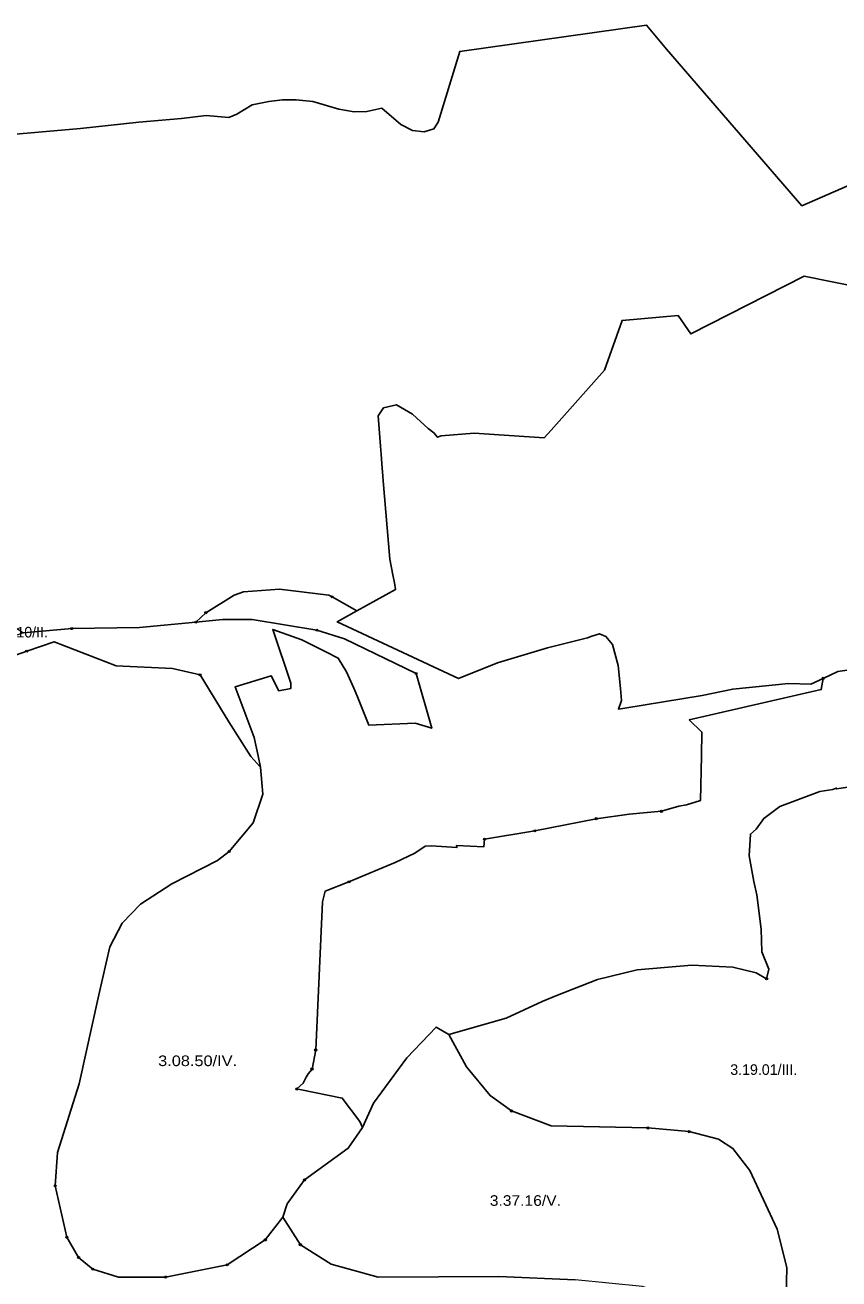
# Model space of a CAD drawing. Extents: x -650455 to -642254, y -1075222 to -1066610.
# Drawn here: x -644838 to -644071, y -1069625 to -1068444 of the extents above; entities that cross this region are included whole.
import ezdxf
from ezdxf.enums import TextEntityAlignment as Align

# ---------------------------------------------------------------- set-up
doc = ezdxf.new("R2010")
doc.units = 0
doc.header["$LTSCALE"] = 4
doc.header["$PDMODE"] = 32
doc.header["$PDSIZE"] = 2
for name, color, linetype, lineweight in [('1', 7, 'Continuous', 25), ('11', 7, 'Continuous', 13), ('13', 7, 'Continuous', 13), ('14', 7, 'Continuous', 13), ('15', 7, 'Continuous', 13), ('16', 7, 'Continuous', 13)]:
    doc.layers.add(name, color=color, linetype=linetype, lineweight=lineweight)
doc.layers.add('2', color=7, linetype='Continuous')

msp = doc.modelspace()

# ---------------------------------------------------------------- linework, layer by layer
at = {"layer": '1'}
for points in [[(-644865.029, -1068548.219), (-644785.549, -1068541.387), (-644730.78, -1068535.476), (-644690.424, -1068532.018), (-644667.364, -1068529.135), (-644646.033, -1068530.865), (-644638.25, -1068527.839), (-644623.837, -1068518.903), (-644608.271, -1068515.731), (-644595.299, -1068514.291), (-644582.328, -1068514.291), (-644566.762, -1068515.875), (-644542.26, -1068523.081), (-644527.847, -1068525.533), (-644515.877, -1068525.233), (-644501.596, -1068522.127), (-644483.899, -1068537.657), (-644472.722, -1068543.249), (-644461.856, -1068544.49), (-644452.542, -1068541.695), (-644448.506, -1068535.484), (-644428.326, -1068468.706), (-644252.29, -1068443.858), (-644233.352, -1068466.531)], [(-644233.352, -1068466.531), (-644105.749, -1068614.065), (-644012.919, -1068573.686)], [(-644024.406, -1068696.372), (-644103.575, -1068680.531), (-644210.376, -1068734.886), (-644222.484, -1068717.492), (-644275.263, -1068722.151), (-644291.718, -1068769.051), (-644342.212, -1068825.639), (-644348.534, -1068832.723), (-644414.741, -1068828.435), (-644445.788, -1068830.92), (-644449.35, -1068832.01), (-644452.802, -1068828.111), (-644458.176, -1068823.819), (-644472.804, -1068810.471), (-644488.017, -1068801.775), (-644500.125, -1068804.57), (-644505.092, -1068812.026), (-644502.911, -1068840.68), (-644502.338, -1068848.206), (-644501.654, -1068857.202), (-644500.772, -1068868.778), (-644500.435, -1068873.213), (-644494.115, -1068947.011), (-644491.207, -1068961.854), (-644489.705, -1068969.518), (-644488.773, -1068975.73), (-644525.181, -1068995.897), (-644548.5, -1068982.501), (-644551.5, -1068981.001), (-644598, -1068975.5), (-644632, -1068978.001), (-644641, -1068981.001), (-644667.5, -1068997.501), (-644677, -1069006.501), (-644730, -1069011.5), (-644794, -1069012.5)], [(-644640, -1069067.501), (-644606, -1069057), (-644598.81, -1069071.02), (-644587.5, -1069069), (-644587.5, -1069064), (-644604.5, -1069013.501), (-644577, -1069023.001), (-644555, -1069034.001), (-644543, -1069040.5), (-644535.13, -1069053.181), (-644529.464, -1069065.769), (-644528, -1069068.5), (-644526.232, -1069072.948), (-644525.83, -1069073.84), (-644525.345, -1069075.177), (-644514.093, -1069103.478), (-644470.37, -1069101.551), (-644454.63, -1069106.281), (-644469.28, -1069054.8), (-644537, -1069022.001), (-644563, -1069014.001), (-644624, -1069004), (-644652, -1069004), (-644677, -1069006.501), (-644667.5, -1068997.501), (-644641, -1068981.001), (-644632, -1068978.001), (-644598, -1068975.5), (-644551.5, -1068981.001), (-644548.5, -1068982.501), (-644525.181, -1068995.897)], [(-644839.5, -1069016.5), (-644794, -1069012.5), (-644730, -1069011.5), (-644677, -1069006.501), (-644652, -1069004), (-644624, -1069004), (-644563, -1069014.001), (-644537, -1069022.001), (-644469.28, -1069054.8), (-644454.63, -1069106.281), (-644470.37, -1069101.551), (-644514.093, -1069103.478), (-644525.345, -1069075.177), (-644525.83, -1069073.84), (-644526.232, -1069072.948), (-644528, -1069068.5), (-644529.464, -1069065.769), (-644535.13, -1069053.181), (-644543, -1069040.5)], [(-644525.181, -1068995.897), (-644543.726, -1069006.168), (-644429.474, -1069059.592), (-644392.528, -1069044.683), (-644345.647, -1069030.706), (-644307.77, -1069021.078), (-644303.667, -1069019.725), (-644296.6, -1069017.395), (-644290.701, -1069019.88), (-644284.181, -1069027.644), (-644278.903, -1069047.211), (-644276.818, -1069069.004), (-644275.887, -1069080.185), (-644278.515, -1069088.547), (-644272.734, -1069087.604), (-644199.819, -1069075.69), (-644170.945, -1069069.479), (-644118.477, -1069064.198), (-644097.468, -1069064.949), (-644085.664, -1069059.379), (-644087.5, -1069070.001), (-644212, -1069098.501), (-644200, -1069110), (-644200.5, -1069132.5), (-644201.5, -1069174.5), (-644214.53, -1069178.601), (-644221.69, -1069179.9), (-644238.23, -1069184.641), (-644268.7, -1069187.421), (-644299.717, -1069191.596), (-644357.5, -1069203), (-644405, -1069211), (-644405.5, -1069218), (-644431.362, -1069216.923), (-644430.91, -1069218.821), (-644454.87, -1069217.05), (-644460.97, -1069217.61), (-644470.64, -1069224.001), (-644489.27, -1069233.04), (-644532.71, -1069251.121)], [(-644794, -1069012.5), (-644839.5, -1069016.5)], [(-644543, -1069040.5), (-644555, -1069034.001), (-644577, -1069023.001), (-644604.5, -1069013.501), (-644587.5, -1069064), (-644587.5, -1069069), (-644598.81, -1069071.02), (-644606, -1069057), (-644640, -1069067.501), (-644622, -1069115.001), (-644618.28, -1069132.421), (-644616, -1069143.001)], [(-644616, -1069143.001), (-644625, -1069133), (-644646, -1069100.5), (-644673, -1069056), (-644699, -1069050.001), (-644752, -1069047.5), (-644810.5, -1069025), (-644836.38, -1069033.691), (-644871, -1069046.001)], [(-644871, -1069046.001), (-644836.38, -1069033.691), (-644810.5, -1069025), (-644752, -1069047.5), (-644699, -1069050.001)], [(-644699, -1069050.001), (-644673, -1069056), (-644646, -1069100.5), (-644625, -1069133), (-644616, -1069143.001)], [(-644357.5, -1069203), (-644299.717, -1069191.596), (-644268.7, -1069187.421), (-644238.23, -1069184.641), (-644221.69, -1069179.9), (-644214.53, -1069178.601), (-644201.5, -1069174.5), (-644200.5, -1069132.5), (-644200, -1069110), (-644212, -1069098.501), (-644087.5, -1069070.001), (-644085.664, -1069059.379), (-644071.881, -1069052.874), (-644052.196, -1069050.206), (-644019.287, -1069058.281), (-643971.567, -1069076.484)], [(-644532.71, -1069251.121), (-644555, -1069260), (-644557.5, -1069270.001), (-644564, -1069409.5), (-644567.5, -1069427.501), (-644571, -1069432.001), (-644572.97, -1069435.121), (-644575.93, -1069440.66), (-644581.87, -1069446.281), (-644578.92, -1069446.801), (-644539, -1069454.881), (-644522.5, -1069477), (-644520, -1069482.5), (-644533.5, -1069502), (-644574.5, -1069532.001), (-644591, -1069554.5), (-644595, -1069567), (-644611.5, -1069588.501), (-644647.5, -1069612), (-644705.5, -1069623.5), (-644750, -1069623.5), (-644774, -1069616), (-644787.5, -1069605.001), (-644798.5, -1069586), (-644809.5, -1069537.5), (-644807.5, -1069506), (-644787, -1069441.5), (-644768.5, -1069357.501), (-644758, -1069312.5), (-644746.5, -1069290.001), (-644729, -1069272), (-644699.5, -1069253.001), (-644656.5, -1069231), (-644645.5, -1069222.5), (-644623, -1069195.501), (-644614, -1069168.501), (-644616, -1069143.001), (-644618.28, -1069132.421), (-644622, -1069115.001), (-644640, -1069067.501)], [(-644616, -1069143.001), (-644614, -1069168.501), (-644623, -1069195.501), (-644645.5, -1069222.5), (-644656.5, -1069231), (-644699.5, -1069253.001), (-644729, -1069272), (-644746.5, -1069290.001), (-644758, -1069312.5), (-644768.5, -1069357.501), (-644787, -1069441.5), (-644807.5, -1069506), (-644809.5, -1069537.5), (-644798.5, -1069586), (-644787.5, -1069605.001), (-644774, -1069616), (-644750, -1069623.5), (-644705.5, -1069623.5), (-644647.5, -1069612), (-644611.5, -1069588.501), (-644595, -1069567), (-644578.5, -1069593.001), (-644549.5, -1069611.5), (-644505, -1069623.5), (-644391.5, -1069623), (-644319.5, -1069626.001)], [(-644209.5, -1069329.501), (-644171, -1069331.5), (-644149, -1069337.001), (-644139, -1069342.501), (-644137, -1069333.501), (-644143.54, -1069317.051), (-644144.05, -1069295.67), (-644148.22, -1069263.22), (-644151.11, -1069250.7), (-644155.37, -1069226.72), (-644154.36, -1069206.06), (-644148.931, -1069201.554), (-644141.5, -1069191.501), (-644126.5, -1069180.001), (-644089, -1069166), (-644076.643, -1069164.135), (-644073.35, -1069162.84), (-644073.229, -1069163.62), (-644062.5, -1069162)], [(-644062.5, -1069162), (-644073.229, -1069163.62), (-644073.35, -1069162.84), (-644076.643, -1069164.135), (-644089, -1069166), (-644126.5, -1069180.001), (-644141.5, -1069191.501), (-644148.931, -1069201.554), (-644154.36, -1069206.06), (-644155.37, -1069226.72), (-644151.11, -1069250.7)], [(-644151.11, -1069250.7), (-644148.22, -1069263.22), (-644144.05, -1069295.67), (-644143.54, -1069317.051), (-644137, -1069333.501), (-644139, -1069342.501), (-644149, -1069337.001), (-644171, -1069331.5), (-644209.5, -1069329.501), (-644261, -1069334.001), (-644298.5, -1069343), (-644337.6, -1069358.4), (-644350.5, -1069364), (-644384.5, -1069379.5), (-644438.5, -1069395.001), (-644450.5, -1069388), (-644478, -1069417), (-644509.5, -1069459.501), (-644520, -1069482.5), (-644522.5, -1069477), (-644539, -1069454.881), (-644578.92, -1069446.801), (-644581.87, -1069446.281), (-644575.93, -1069440.66), (-644572.97, -1069435.121), (-644571, -1069432.001), (-644567.5, -1069427.501), (-644564, -1069409.5), (-644557.5, -1069270.001), (-644555, -1069260), (-644532.71, -1069251.121), (-644489.27, -1069233.04), (-644470.64, -1069224.001), (-644460.97, -1069217.61), (-644454.87, -1069217.05), (-644430.91, -1069218.821), (-644431.362, -1069216.923), (-644405.5, -1069218), (-644405, -1069211), (-644357.5, -1069203)], [(-644121, -1069656), (-644120, -1069614.5), (-644129, -1069578.5), (-644155, -1069523), (-644171, -1069502.5), (-644184.5, -1069493.5), (-644212, -1069486.5), (-644251, -1069483.001), (-644342, -1069481), (-644379.5, -1069467.001), (-644399.5, -1069452.5), (-644422, -1069425.5), (-644438.5, -1069395.001), (-644384.5, -1069379.5), (-644350.5, -1069364), (-644337.6, -1069358.4), (-644298.5, -1069343), (-644261, -1069334.001), (-644209.5, -1069329.501)], [(-644319.5, -1069626.001), (-644391.5, -1069623), (-644505, -1069623.5), (-644549.5, -1069611.5), (-644578.5, -1069593.001), (-644595, -1069567), (-644591, -1069554.5), (-644574.5, -1069532.001), (-644533.5, -1069502), (-644520, -1069482.5), (-644509.5, -1069459.501), (-644478, -1069417), (-644450.5, -1069388), (-644438.5, -1069395.001), (-644422, -1069425.5), (-644399.5, -1069452.5), (-644379.5, -1069467.001), (-644342, -1069481), (-644251, -1069483.001), (-644212, -1069486.5), (-644184.5, -1069493.5), (-644171, -1069502.5), (-644155, -1069523), (-644129, -1069578.5), (-644120, -1069614.5), (-644121, -1069656)]]:
    msp.add_lwpolyline(points, dxfattribs=at)
at = {"layer": '11'}
for points in [[(-644012.919, -1068573.686), (-644105.749, -1068614.065), (-644233.352, -1068466.531), (-644252.29, -1068443.858), (-644428.326, -1068468.706), (-644448.506, -1068535.484)], [(-644448.506, -1068535.484), (-644452.542, -1068541.695), (-644461.856, -1068544.49), (-644472.722, -1068543.249), (-644483.899, -1068537.657), (-644501.596, -1068522.127), (-644515.877, -1068525.233), (-644527.847, -1068525.533), (-644542.26, -1068523.081), (-644566.762, -1068515.875), (-644582.328, -1068514.291), (-644595.299, -1068514.291), (-644608.271, -1068515.731), (-644623.837, -1068518.903), (-644638.25, -1068527.839), (-644646.033, -1068530.865), (-644667.364, -1068529.135), (-644690.424, -1068532.018), (-644730.78, -1068535.476), (-644785.549, -1068541.387), (-644865.029, -1068548.219)], [(-644667.5, -1068997.501), (-644641, -1068981.001), (-644632, -1068978.001), (-644598, -1068975.5), (-644551.5, -1068981.001), (-644548.5, -1068982.501), (-644525.181, -1068995.897), (-644488.773, -1068975.73), (-644489.705, -1068969.518), (-644491.207, -1068961.854), (-644494.115, -1068947.011), (-644500.435, -1068873.213), (-644500.772, -1068868.778), (-644501.654, -1068857.202), (-644502.338, -1068848.206), (-644502.911, -1068840.68), (-644505.092, -1068812.026), (-644500.125, -1068804.57), (-644488.017, -1068801.775), (-644472.804, -1068810.471), (-644458.176, -1068823.819), (-644452.802, -1068828.111), (-644449.35, -1068832.01), (-644445.788, -1068830.92), (-644414.741, -1068828.435), (-644348.534, -1068832.723), (-644342.212, -1068825.639), (-644291.718, -1068769.051), (-644275.263, -1068722.151), (-644222.484, -1068717.492), (-644210.376, -1068734.886), (-644103.575, -1068680.531), (-644024.406, -1068696.372)], [(-644884.5, -1069007), (-644872.563, -1069007.374), (-644875.563, -1068993.501), (-644867.701, -1068989.497), (-644855.56, -1068983.38), (-644851.16, -1069004.211), (-644851.147, -1069004.26), (-644850.813, -1069004.126), (-644849.51, -1069009.955), (-644839.5, -1069016.5), (-644794, -1069012.5), (-644730, -1069011.5), (-644677, -1069006.501), (-644667.5, -1068997.501)], [(-644809.5, -1069537.5), (-644807.5, -1069506), (-644787, -1069441.5), (-644768.5, -1069357.501), (-644758, -1069312.5), (-644746.5, -1069290.001), (-644729, -1069272), (-644699.5, -1069253.001), (-644656.5, -1069231), (-644645.5, -1069222.5), (-644623, -1069195.501), (-644614, -1069168.501), (-644616, -1069143.001), (-644625, -1069133), (-644646, -1069100.5), (-644673, -1069056), (-644699, -1069050.001), (-644752, -1069047.5), (-644810.5, -1069025), (-644836.38, -1069033.691), (-644871, -1069046.001)], [(-644787.5, -1069605.001), (-644798.5, -1069586), (-644809.5, -1069537.5)], [(-644578.5, -1069593.001), (-644595, -1069567), (-644611.5, -1069588.501)], [(-644611.5, -1069588.501), (-644647.5, -1069612), (-644705.5, -1069623.5)], [(-644217.5, -1069644.5), (-644256, -1069632.5), (-644319.5, -1069626.001), (-644391.5, -1069623), (-644505, -1069623.5), (-644549.5, -1069611.5), (-644578.5, -1069593.001)], [(-644705.5, -1069623.5), (-644750, -1069623.5), (-644774, -1069616), (-644787.5, -1069605.001)]]:
    msp.add_lwpolyline(points, dxfattribs=at)
for p in [(-644667.5, -1068997.501), (-644809.5, -1069537.5), (-644611.5, -1069588.501), (-644578.5, -1069593.001), (-644787.5, -1069605.001), (-644705.5, -1069623.5)]:
    msp.add_point(p, dxfattribs=at)
at = {"layer": '13'}
msp.add_line((-644251, -1069483.001), (-644212, -1069486.5), dxfattribs=at)
for points in [[(-644062.5, -1069162), (-644073.229, -1069163.62), (-644073.35, -1069162.84), (-644076.643, -1069164.135), (-644089, -1069166), (-644126.5, -1069180.001), (-644141.5, -1069191.501), (-644148.931, -1069201.554), (-644154.36, -1069206.06), (-644155.37, -1069226.72), (-644151.11, -1069250.7), (-644148.22, -1069263.22), (-644144.05, -1069295.67), (-644143.54, -1069317.051), (-644137, -1069333.501), (-644139, -1069342.501)], [(-644139, -1069342.501), (-644149, -1069337.001), (-644171, -1069331.5), (-644209.5, -1069329.501), (-644261, -1069334.001), (-644298.5, -1069343), (-644337.6, -1069358.4), (-644350.5, -1069364), (-644384.5, -1069379.5), (-644438.5, -1069395.001), (-644422, -1069425.5), (-644399.5, -1069452.5), (-644379.5, -1069467.001)], [(-644379.5, -1069467.001), (-644342, -1069481), (-644251, -1069483.001)], [(-644212, -1069486.5), (-644184.5, -1069493.5), (-644171, -1069502.5), (-644155, -1069523), (-644129, -1069578.5), (-644120, -1069614.5), (-644121, -1069656), (-644126, -1069675.5), (-644140, -1069691.001), (-644156, -1069689), (-644140, -1069712), (-644126, -1069716.5), (-644097.5, -1069715.001), (-644062, -1069701), (-644014, -1069639.5), (-643984, -1069608)]]:
    msp.add_lwpolyline(points, dxfattribs=at)
for p in [(-644139, -1069342.501), (-644379.5, -1069467.001), (-644251, -1069483.001), (-644212, -1069486.5)]:
    msp.add_point(p, dxfattribs=at)
at = {"layer": '14'}
for p, q in [((-644357.5, -1069203), (-644299.717, -1069191.596)), ((-644798.5, -1069586), (-644787.5, -1069605.001)), ((-644787.5, -1069605.001), (-644774, -1069616))]:
    msp.add_line(p, q, dxfattribs=at)
for points in [[(-644548.5, -1068982.501), (-644551.5, -1068981.001), (-644598, -1068975.5), (-644632, -1068978.001), (-644641, -1068981.001), (-644667.5, -1068997.501), (-644677, -1069006.501)], [(-644085.664, -1069059.379), (-644097.468, -1069064.949), (-644118.477, -1069064.198), (-644170.945, -1069069.479), (-644199.819, -1069075.69), (-644272.734, -1069087.604), (-644278.515, -1069088.547), (-644275.887, -1069080.185), (-644276.818, -1069069.004), (-644278.903, -1069047.211), (-644284.181, -1069027.644), (-644290.701, -1069019.88), (-644296.6, -1069017.395), (-644303.667, -1069019.725), (-644307.77, -1069021.078), (-644345.647, -1069030.706), (-644392.528, -1069044.683), (-644429.474, -1069059.592), (-644543.726, -1069006.168), (-644525.181, -1068995.897), (-644548.5, -1068982.501)], [(-644677, -1069006.501), (-644652, -1069004), (-644624, -1069004), (-644563, -1069014.001)], [(-644563, -1069014.001), (-644537, -1069022.001), (-644469.28, -1069054.8), (-644454.63, -1069106.281), (-644470.37, -1069101.551), (-644514.093, -1069103.478), (-644525.345, -1069075.177), (-644525.83, -1069073.84), (-644526.232, -1069072.948), (-644528, -1069068.5), (-644529.464, -1069065.769), (-644535.13, -1069053.181), (-644543, -1069040.5), (-644555, -1069034.001), (-644577, -1069023.001), (-644604.5, -1069013.501), (-644587.5, -1069064), (-644587.5, -1069069), (-644598.81, -1069071.02), (-644606, -1069057), (-644640, -1069067.501), (-644622, -1069115.001), (-644618.28, -1069132.421), (-644616, -1069143.001), (-644614, -1069168.501), (-644623, -1069195.501), (-644645.5, -1069222.5)], [(-644299.717, -1069191.596), (-644268.7, -1069187.421), (-644238.23, -1069184.641), (-644221.69, -1069179.9), (-644214.53, -1069178.601), (-644201.5, -1069174.5), (-644200.5, -1069132.5), (-644200, -1069110), (-644212, -1069098.501), (-644087.5, -1069070.001), (-644085.664, -1069059.379)], [(-644532.71, -1069251.121), (-644489.27, -1069233.04), (-644470.64, -1069224.001), (-644460.97, -1069217.61), (-644454.87, -1069217.05), (-644430.91, -1069218.821), (-644431.362, -1069216.923), (-644405.5, -1069218), (-644405, -1069211), (-644357.5, -1069203)], [(-644645.5, -1069222.5), (-644656.5, -1069231), (-644699.5, -1069253.001), (-644729, -1069272), (-644746.5, -1069290.001), (-644758, -1069312.5), (-644768.5, -1069357.501), (-644787, -1069441.5), (-644807.5, -1069506), (-644809.5, -1069537.5), (-644798.5, -1069586)], [(-644567.5, -1069427.501), (-644564, -1069409.5), (-644557.5, -1069270.001), (-644555, -1069260), (-644532.71, -1069251.121)], [(-644574.5, -1069532.001), (-644533.5, -1069502), (-644520, -1069482.5), (-644522.5, -1069477), (-644539, -1069454.881), (-644578.92, -1069446.801), (-644581.87, -1069446.281), (-644575.93, -1069440.66), (-644572.97, -1069435.121), (-644571, -1069432.001), (-644567.5, -1069427.501)], [(-644647.5, -1069612), (-644611.5, -1069588.501), (-644595, -1069567), (-644591, -1069554.5), (-644574.5, -1069532.001)], [(-644774, -1069616), (-644750, -1069623.5), (-644705.5, -1069623.5), (-644647.5, -1069612)]]:
    msp.add_lwpolyline(points, dxfattribs=at)
for p in [(-644548.5, -1068982.501), (-644677, -1069006.501), (-644563, -1069014.001), (-644085.664, -1069059.379), (-644299.717, -1069191.596), (-644357.5, -1069203), (-644645.5, -1069222.5), (-644532.71, -1069251.121), (-644567.5, -1069427.501), (-644574.5, -1069532.001), (-644798.5, -1069586), (-644787.5, -1069605.001), (-644774, -1069616), (-644647.5, -1069612)]:
    msp.add_point(p, dxfattribs=at)
at = {"layer": '15'}
msp.add_lwpolyline([(-644121, -1069656), (-644120, -1069614.5), (-644129, -1069578.5), (-644155, -1069523), (-644171, -1069502.5), (-644184.5, -1069493.5), (-644212, -1069486.5), (-644251, -1069483.001), (-644342, -1069481), (-644379.5, -1069467.001), (-644399.5, -1069452.5), (-644422, -1069425.5), (-644438.5, -1069395.001), (-644450.5, -1069388), (-644478, -1069417), (-644509.5, -1069459.501), (-644520, -1069482.5), (-644533.5, -1069502), (-644574.5, -1069532.001), (-644591, -1069554.5), (-644595, -1069567), (-644578.5, -1069593.001), (-644549.5, -1069611.5), (-644505, -1069623.5), (-644391.5, -1069623), (-644319.5, -1069626.001)], dxfattribs=at)
at = {"layer": '16'}
for points in [[(-644469.28, -1069054.8), (-644537, -1069022.001), (-644563, -1069014.001), (-644624, -1069004), (-644652, -1069004), (-644677, -1069006.501), (-644730, -1069011.5), (-644794, -1069012.5)], [(-644794, -1069012.5), (-644839.5, -1069016.5), (-644847.621, -1069019.397), (-644847.625, -1069019.376), (-644848.375, -1069014.875), (-644939.937, -1069052.376), (-644941.25, -1069052.876), (-644936, -1069065.875), (-644935.995, -1069065.887), (-644932.75, -1069073.5), (-644932.672, -1069073.465), (-644917.772, -1069066.77), (-644888.516, -1069053.508), (-644887.558, -1069053.097), (-644871, -1069046.001), (-644836.38, -1069033.691)], [(-644673, -1069056), (-644646, -1069100.5), (-644625, -1069133), (-644616, -1069143.001), (-644618.28, -1069132.421), (-644622, -1069115.001), (-644640, -1069067.501), (-644606, -1069057), (-644598.81, -1069071.02), (-644587.5, -1069069), (-644587.5, -1069064), (-644604.5, -1069013.501), (-644577, -1069023.001), (-644555, -1069034.001), (-644543, -1069040.5), (-644535.13, -1069053.181), (-644529.464, -1069065.769), (-644528, -1069068.5), (-644526.232, -1069072.948), (-644525.83, -1069073.84), (-644525.345, -1069075.177), (-644514.093, -1069103.478), (-644470.37, -1069101.551), (-644454.63, -1069106.281), (-644469.28, -1069054.8)], [(-644836.38, -1069033.691), (-644810.5, -1069025), (-644752, -1069047.5), (-644699, -1069050.001), (-644673, -1069056)], [(-643888.83, -1069111.611), (-643890.13, -1069111.65), (-643891.55, -1069111.13), (-643891.564, -1069111.125), (-643909.5, -1069108.5), (-643945.5, -1069094), (-643971.567, -1069076.484), (-644019.287, -1069058.281), (-644052.196, -1069050.206), (-644071.881, -1069052.874), (-644085.664, -1069059.379), (-644087.5, -1069070.001), (-644212, -1069098.501), (-644200, -1069110), (-644200.5, -1069132.5), (-644201.5, -1069174.5), (-644214.53, -1069178.601), (-644221.69, -1069179.9), (-644238.23, -1069184.641)], [(-644581.87, -1069446.281), (-644578.92, -1069446.801), (-644539, -1069454.881), (-644522.5, -1069477), (-644520, -1069482.5), (-644509.5, -1069459.501), (-644478, -1069417), (-644450.5, -1069388), (-644438.5, -1069395.001), (-644384.5, -1069379.5), (-644350.5, -1069364), (-644337.6, -1069358.4), (-644298.5, -1069343), (-644261, -1069334.001), (-644209.5, -1069329.501), (-644171, -1069331.5), (-644149, -1069337.001), (-644139, -1069342.501), (-644137, -1069333.501), (-644143.54, -1069317.051), (-644144.05, -1069295.67), (-644148.22, -1069263.22), (-644151.11, -1069250.7), (-644155.37, -1069226.72), (-644154.36, -1069206.06), (-644148.931, -1069201.554), (-644141.5, -1069191.501), (-644126.5, -1069180.001), (-644089, -1069166), (-644076.643, -1069164.135), (-644073.35, -1069162.84), (-644073.229, -1069163.62), (-644062.5, -1069162)], [(-644238.23, -1069184.641), (-644268.7, -1069187.421), (-644299.717, -1069191.596), (-644357.5, -1069203), (-644405, -1069211)], [(-644405, -1069211), (-644405.5, -1069218), (-644431.362, -1069216.923), (-644430.91, -1069218.821), (-644454.87, -1069217.05), (-644460.97, -1069217.61), (-644470.64, -1069224.001), (-644489.27, -1069233.04), (-644532.71, -1069251.121), (-644555, -1069260), (-644557.5, -1069270.001), (-644564, -1069409.5)], [(-644564, -1069409.5), (-644567.5, -1069427.501), (-644571, -1069432.001), (-644572.97, -1069435.121), (-644575.93, -1069440.66), (-644581.87, -1069446.281)]]:
    msp.add_lwpolyline(points, dxfattribs=at)
for p in [(-644794, -1069012.5), (-644836.38, -1069033.691), (-644469.28, -1069054.8), (-644673, -1069056), (-644238.23, -1069184.641), (-644405, -1069211), (-644564, -1069409.5), (-644581.87, -1069446.281)]:
    msp.add_point(p, dxfattribs=at)

# ---------------------------------------------------------------- texts
at = {"layer": '2'}
for s, p in [('3.10.10/II.', (-644846.118, -1069020.872)), ('3.19.01/III.', (-644141.691, -1069433.015))]:
    msp.add_text(s, height=10, dxfattribs=at).set_placement(p, align=Align.CENTER)
for s, width, p in [('3.08.50/IV.', 1.15, (-644675.312, -1069424.737)), ('3.37.16/V.', 1.1, (-644366.39, -1069556.37))]:
    msp.add_text(s, height=10, dxfattribs=dict(at, width=width)).set_placement(p, align=Align.CENTER)

doc.saveas('drawing.dxf')
